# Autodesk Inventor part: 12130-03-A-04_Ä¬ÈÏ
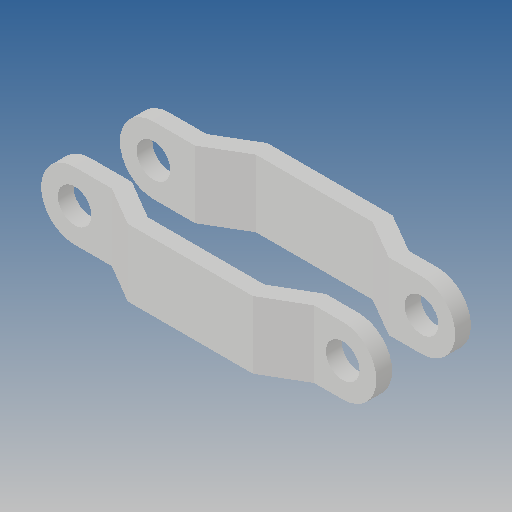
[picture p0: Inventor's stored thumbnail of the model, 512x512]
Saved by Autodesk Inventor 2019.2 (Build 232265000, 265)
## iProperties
Created: 2010-06
Part Number: 12130-03-A-04_Ä¬ÈÏ
Material: Ogólny
Document SubType Name: Modeling
Designer: CADENGINEERING4
Density: 1 g/cm^3
Appearance: Domyślna
Author: CADENGINEERING4
Revision Number: ÈÎºÎ
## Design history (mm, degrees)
feature "NONE"
feature "NONE:1"
node "Bryła1"
node "Bryła2"
